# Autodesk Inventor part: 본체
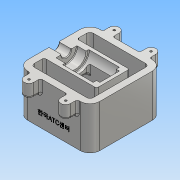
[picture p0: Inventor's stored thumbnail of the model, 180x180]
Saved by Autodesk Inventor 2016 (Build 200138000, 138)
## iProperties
Created: 2018-01
Part Number: 본체
Material: 알루미늄 6061
Document SubType Name: Modeling
Designer: Administrator
Density: 2.7 g/cm^3
Appearance: 알루미늄 - 평지
Mass: 995.263 g
Surface Area: 834.768 cm^2
Volume: 368.616 cm^3
Author: Administrator
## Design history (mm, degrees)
sketch "스케치1"
  geometry: L1 (-55, 55)-(55, 55); L2 (55, 55)-(55, -55); L3 (55, -55)-(-55, -55); L4 (-55, -55)-(-55, 55); L5 (-55, 55)-(55, -55); L6 (55, 55)-(-55, -55); 1 further point
  constraints: 12 end point, 2 midpoint, 2 parallel, 1 horizontal, 1 perpendicular
  dimensions: "d0" = 110 distance of L2.end L3.end; "d1" = 110 distance of L1.end L2.end
extrude "돌출1" new body sketch "스케치1" distance "d2" = 65; taper "d3" = 0 deg
sketch "스케치2"
  geometry: L1 (-55, 55)-(55, 55) reference; L2 (-55, -55)-(-55, 55) reference; L3 (55, 55)-(55, -55) reference; L4 (0, 0)-(55, 0); L5 (-45, 45)-(-45, 25); L6 (-45, 25)-(35, 25); L7 (35, 25)-(35, 0); L8 (-45, 45)-(45, 45); L9 (45, 45)-(45, 0); L10 (-45, -45)-(-45, -25); L11 (-45, -25)-(35, -25); L12 (35, -25)-(35, 0); L13 (-45, -45)-(45, -45); L14 (45, -45)-(45, 0)
  constraints: 22 end point, 4 symmetric about line, 3 perpendicular, 2 point on line, 1 horizontal, 1 midpoint, 1 vertical
  dimensions: "d4" = 30 distance between parallel lines of L1 L6; "d5" = 10 distance between parallel lines of L2 L5; "d6" = 10 distance between parallel lines of L3 L9; "d7" = 10 distance between parallel lines of L1 L8; "d8" = 20 distance between parallel lines of L3 L12
extrude "돌출2" cut sketch "스케치2" stored distance "d9" = 65; taper "d10" = 0 deg
sketch "스케치3"
  geometry: L1 (-55, 55)-(55, 55) reference; L2 (-55, -55)-(-55, 55) reference; L3 (-35.5, 65)-(-20.5, 65); L4 (-20.5, 65)-(-20.5, 55); L5 (-20.5, 55)-(-35.5, 55); L6 (-35.5, 55)-(-35.5, 65); L7 (-35.5, 65)-(-20.5, 55); L8 (-20.5, 65)-(-35.5, 55); L9 (0, 0)-(81.697, 0); L10 (0, 0)-(0, 41.333); L11 (20.5, 55)-(35.5, 55); L12 (35.5, 65)-(20.5, 65); L13 (35.5, 55)-(35.5, 65); L14 (35.5, 65)-(20.5, 55); L15 (20.5, 65)-(35.5, 55); L16 (20.5, 65)-(20.5, 55); L17 (20.5, -55)-(35.5, -55); L18 (35.5, -55)-(35.5, -65); L19 (20.5, -65)-(20.5, -55); L20 (35.5, -65)-(20.5, -65); L21 (35.5, -65)-(20.5, -55); L22 (20.5, -65)-(35.5, -55); L23 (-20.5, -65)-(-20.5, -55); L24 (-20.5, -55)-(-35.5, -55); L25 (-35.5, -55)-(-35.5, -65); L26 (-35.5, -65)-(-20.5, -55); L27 (-20.5, -65)-(-35.5, -55); L28 (-35.5, -65)-(-20.5, -65); A1 r 7.5 centre (-28, 65) between (-20.5, 65) and (-35.5, 65); A2 r 7.5 centre (28, 65) between (35.5, 65) and (20.5, 65); A3 r 7.5 centre (28, -65) between (20.5, -65) and (35.5, -65); A4 r 7.5 centre (-28, -65) between (-35.5, -65) and (-20.5, -65); 8 further points
  constraints: 52 end point, 21 symmetric about line, 10 midpoint, 8 point on circle, 4 centre point, 2 horizontal, 2 parallel, 1 perpendicular, 1 point on line, 1 vertical, 3 other
  dimensions: "d11" = 27 distance from line of L2 A1.centre; "d12" = 10 distance from line of L1 A1.centre; "d13" = 7.5 radius of A1
extrude "돌출3" join sketch "스케치3" distance "d14" = 20; taper "d15" = 0 deg
sketch "스케치4"
  geometry: L1 (35, -25)-(35, 25) reference; L2 (-55, -55)-(-55, 55) reference; L3 (-55, 0)-(35, 0); L4 (-55, 7.5)-(-36, 7.5); L5 (-36, 7.5)-(-36, 16); L6 (-36, 16)-(-22, 16); L7 (-22, 16)-(-22, 20); L8 (-22, 20)-(25, 20); L9 (25, 20)-(25, 15); L10 (25, 15)-(30, 15); L11 (30, 15)-(30, 0); 1 further point
  constraints: 18 end point, 7 perpendicular, 2 midpoint, 2 point on line, 1 horizontal
  dimensions: "d16" = 15 diameter of L4 L3; "d17" = 32 diameter of L6 L3; "d18" = 40 diameter of L8 L3; "d19" = 30 diameter of L10 L3; "d20" = 5 distance between parallel lines of L11 L9; "d21" = 47 distance between parallel lines of L7 L9; "d22" = 14 distance between parallel lines of L5 L7; "d23" = 19 distance between parallel lines of L2 L5
revolve "회전1" sketch "스케치4" stored, may be unused: angle "d24" = 90 deg
sketch "스케치5"
  geometry: L1 (-35, -35)-(45, -56.436); L2 (45, -56.436)-(45, -65); L3 (-45, -65)-(45, -65) reference; L4 (55, 0)-(55, -65) reference; L5 (-35, 0)-(-35, -65) reference; 1 further point
  constraints: 4 end point, 2 point on line, 1 vertical
  dimensions: "d25" = 30 distance from line of L3 L1.start; "d26" = 105 deg angle of L2 L1; "d27" = 10 distance between parallel lines of L4 L2
extrude "돌출4" cut sketch "스케치5" stored distance "d28" = 50; taper "d29" = 0 deg
sketch "스케치6"
  geometry: L1 (55, 0)-(55, -65) reference; L2 (55, -53.939)-(-20, -33.843); L3 (-20, -33.843)-(-20, 0); L4 (-25, -20)-(22, -20) reference; L5 (-20, 0)-(17, 0); L6 (17, 0)-(17, -25.757); L7 (17, -25.757)-(55, -35.939); L8 (-35, -35)-(45, -56.436) reference; L9 (22, 0)-(-25, 0) reference; 2 further points
  constraints: 10 end point, 3 perpendicular, 2 midpoint, 2 parallel, 2 point on line
  dimensions: "d30" = 5 distance between parallel lines of L8 L2; "d31" = 18 distance of L2.start L7.end; "d32" = 37 distance between parallel lines of L3 L6
extrude "돌출5" cut sketch "스케치6" stored distance "d33" = 30; taper "d34" = 0 deg
sketch "스케치7"
  geometry: L1 (0, 65)-(0, 0) reference; L2 (110, 0)-(0, 0) reference; 2 further points
  constraints: 1 other
  dimensions: "d35" = 20 distance from line of L2 point (55, 20); "d36" = 55 distance from line of L1 point (55, 20)
feature "엠보싱1" sketch "스케치7" dims "d0" = 110, "d1" = 110, "d4" = 30, "d5" = 10, "d6" = 10, "d7" = 10, "d8" = 20, "d37" = 0.5, "d38" = 0
hole "구멍1" diameter "d41" = 3.242; stored, may be unused: countersink angle "d45" = 90 deg, drill point angle "d47" = 118 deg; dims "d42" = 9, "d43" = 4, "d44" = 2, "d46" = 11, "d62" = 10, "d63" = 10
fillet "모깎기1" dims "d48" = 15
fillet "모깎기2" dims "d49" = 5
fillet "모깎기3" dims "d50" = 3
fillet "모깎기4" dims "d51" = 1
fillet "모깎기5" dims "d52" = 3
fillet "모깎기6" dims "d53" = 3
fillet "모깎기7" dims "d54" = 3
fillet "모깎기8" dims "d55" = 3
fillet "모깎기9" dims "d56" = 3
fillet "모깎기10" dims "d57" = 3
chamfer "모따기1" distance "d58" = 1; stored, may be unused: second distance "d59" = 2, angle "d60" = 45 deg
fillet "모깎기11" dims "d61" = 3
node "솔리드1"
mirror "대칭1"
mirror "대칭2"
node "작업 평면1"
